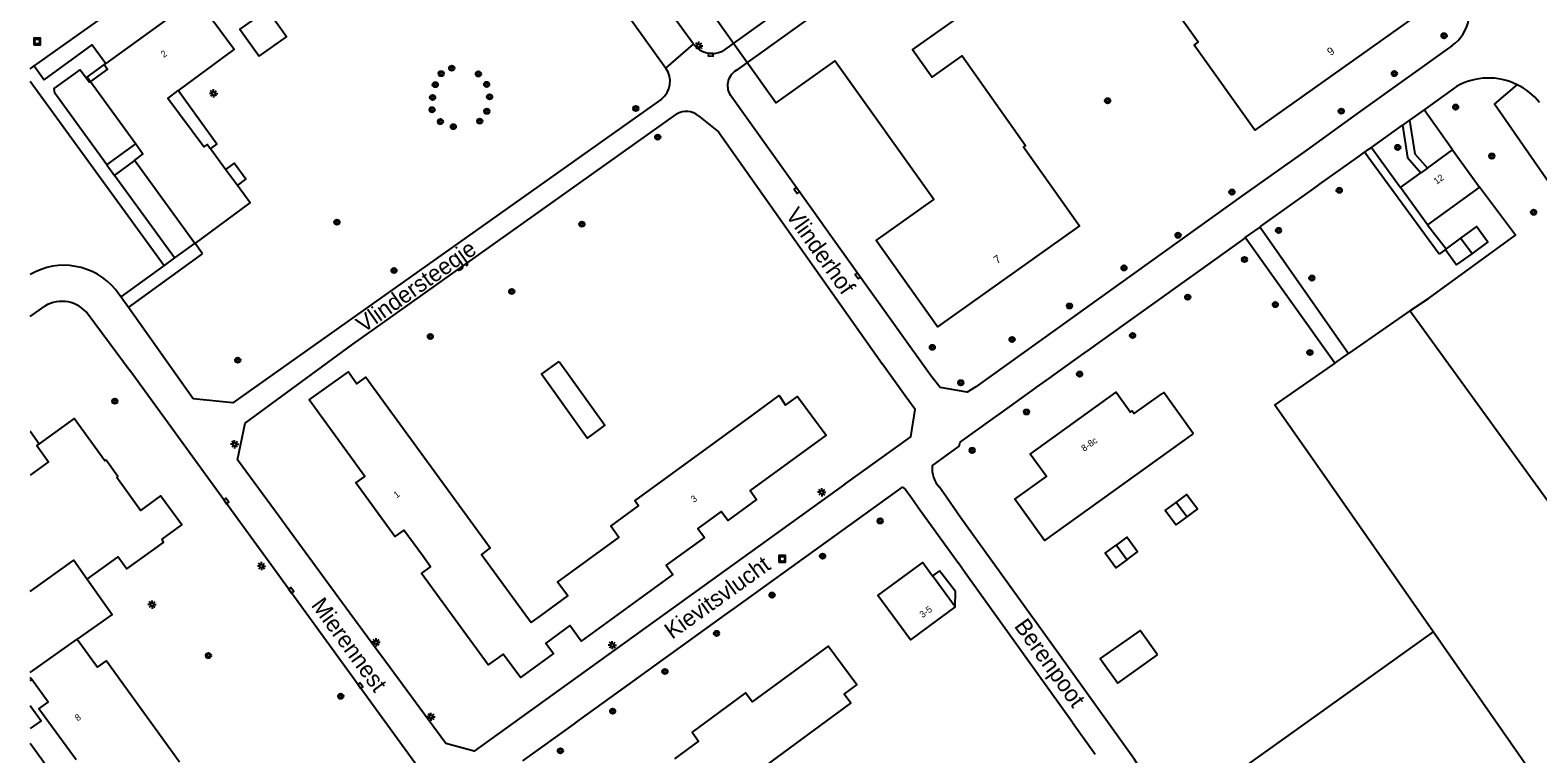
# Model space of a CAD drawing. Extents: x 141000 to 143000, y 400580 to 403500.
# Drawn here: x 141000 to 141228, y 402914.6 to 403024.1 of the extents above; entities that cross this region are included whole.
import ezdxf

# ---------------------------------------------------------------- set-up
doc = ezdxf.new("R2010")
doc.units = 0
for name, color, linetype in [('gg-afsc-erfafscheiding', 7, 'Continuous'), ('gg-afsc-muur', 7, 'Continuous'), ('gg-anno-huisnummerreeks BGT', 7, 'Continuous'), ('gg-anno-openbare ruimte label', 7, 'Continuous'), ('gg-bbg-bijgebouw', 7, 'Continuous'), ('gg-bbg-hoofdgebouw', 7, 'Continuous'), ('gg-bbg-luifel en loopbrug', 7, 'Continuous'), ('gg-bbg-overig bouwwerk', 7, 'Continuous'), ('gg-bbg-tussenscheiding', 7, 'Continuous'), ('gg-knt-verharding', 7, 'Continuous'), ('gg-knt-verharding nz', 7, 'Continuous'), ('gt-anno-plantopografie huisnummer', 7, 'Continuous'), ('gt-bbg-plantopografie pand', 7, 'Continuous'), ('gt-grn-groengrens', 7, 'Continuous'), ('gt-grn-vlakafsluiter', 7, 'Continuous'), ('gt-grn-weggrens', 7, 'Continuous'), ('gt-symb-boom', 7, 'Continuous'), ('gt-symb-kolk', 7, 'Continuous'), ('gt-symb-lichtmast', 7, 'Continuous'), ('gt-symb-rioolschacht', 7, 'Continuous')]:
    doc.layers.add(name, color=color, linetype=linetype)

# ---------------------------------------------------------------- blocks, each defined once
blk = doc.blocks.new('gt0-RS')
at = {"layer": 'gt-symb-rioolschacht'}
blk.add_lwpolyline([(-0.5, -0.5), (0.5, -0.5), (0.5, 0.5), (-0.5, 0.5)], close=True, dxfattribs=at)
blk.add_circle((0, 0), 0.375, dxfattribs=at)
blk = doc.blocks.new('gt0-KOLK')
at = {"layer": 'gt-symb-kolk'}
blk.add_lwpolyline([(0, 0), (0.37, 0), (0.37, 0.4), (-0.38, 0.4), (-0.38, 0), (0, 0)], dxfattribs=at)
blk = doc.blocks.new('gt0-LMAST')
at = {"layer": 'gt-symb-lichtmast'}
for p, q in [((-0.18, 0.17), (-0.45, 0.44)), ((-0.01, 0.25), (-0.01, 0.62)), ((0.17, 0.17), (0.44, 0.44)), ((-0.26, 0), (-0.63, 0)), ((-0.18, -0.18), (-0.45, -0.45)), ((-0.01, -0.25), (-0.01, -0.63)), ((0.44, -0.45), (0.17, -0.18)), ((0.24, 0), (0.62, 0))]:
    blk.add_line(p, q, dxfattribs=at)
blk.add_circle((-0.01, 0), 0.25, dxfattribs=at)
blk = doc.blocks.new('gt0-BOOM')
at = {"layer": 'gt-symb-boom'}
for radius in [0.4, 0.2]:
    blk.add_circle((0, 0), radius, dxfattribs=at)

msp = doc.modelspace()

# ---------------------------------------------------------------- linework, layer by layer
at = {"layer": 'gg-afsc-erfafscheiding'}
msp.add_lwpolyline([(141197.28, 402973.71), (141188.23, 402967.39), (141194.62, 402958.3)], dxfattribs=at)
at = {"layer": 'gg-afsc-muur'}
for points in [[(141002.1, 403016.55), (141009.38, 403021.86), (141011.43, 403019.05)], [(141000, 402963.36), (141000.03, 402963.39), (141001.35, 402961.53)]]:
    msp.add_lwpolyline(points, dxfattribs=at)
at = {"layer": 'gg-bbg-bijgebouw'}
for p, q in [((141216.29, 402992.6), (141214.09, 402990.99)), ((141218.03, 402990.27), (141216.29, 402992.6))]:
    msp.add_line(p, q, dxfattribs=at)
for points in [[(141034.65, 403020.12), (141038.76, 403023.06), (141035.82, 403027.17), (141031.71, 403024.23), (141034.65, 403020.12)], [(141214.09, 402990.99), (141213.98, 402990.91), (141214, 402990.88)], [(141214, 402990.88), (141215.7, 402988.56), (141218.03, 402990.27)], [(141079.99, 402973.98), (141086.91, 402964.32), (141084.22, 402962.39), (141077.3, 402972.05), (141079.99, 402973.98)], [(141174.88, 402950.45), (141173.23, 402949.24), (141171.62, 402951.42), (141173.27, 402952.63)], [(141173.27, 402952.63), (141174.92, 402953.84), (141176.52, 402951.66), (141174.88, 402950.45)], [(141165.81, 402943.99), (141167.46, 402945.2), (141165.85, 402947.39), (141164.2, 402946.18)], [(141165.81, 402943.99), (141164.16, 402942.78), (141162.55, 402944.97), (141164.2, 402946.18)]]:
    msp.add_lwpolyline(points, dxfattribs=at)
at = {"layer": 'gg-bbg-hoofdgebouw'}
for p, q in [((141011.43, 403019.05), (141011.18, 403018.87)), ((141009.11, 403016.3), (141015.96, 403006.87)), ((141015.81, 403004.34), (141024.89, 402991.85)), ((141029.56, 403002.99), (141027.25, 403006.11)), ((141211.28, 403003.22), (141215.06, 403005.96)), ((141215.06, 403005.96), (141219.13, 403000.34)), ((141031.35, 403000.58), (141029.56, 403002.99)), ((141207.2, 403000.27), (141210.3, 403002.51)), ((141211.28, 403003.22), (141210.3, 403002.51)), ((141211.27, 402994.65), (141207.2, 403000.27)), ((141219.13, 403000.34), (141211.27, 402994.65)), ((141024.89, 402991.85), (141024.93, 402991.8)), ((141139.89, 402936.88), (141136.44, 402941.54)), ((141000, 402926.93), (141007.12, 402931.96)), ((141000, 402926.24), (141000.26, 402925.89))]:
    msp.add_line(p, q, dxfattribs=at)
for points in [[(141025.45, 403028.48), (141025.08, 403028.99), (141011.43, 403019.05)], [(141022.4, 403014.93), (141022.57, 403015.05), (141030.83, 403021.16), (141027.52, 403025.66)], [(141011.18, 403018.87), (141011.68, 403018.18), (141009.11, 403016.3)], [(141027.25, 403006.11), (141027.14, 403006.26), (141026.76, 403006.77), (141026.28, 403006.41), (141020.83, 403013.76), (141022.4, 403014.93)], [(141015.96, 403006.87), (141017.06, 403005.35), (141015.76, 403004.41), (141015.81, 403004.34)], [(141024.93, 402991.8), (141033.28, 402997.97), (141031.35, 403000.58)], [(141075.75, 402934.47), (141077.1, 402935.46), (141081.28, 402938.51), (141079.75, 402940.61), (141089.03, 402947.37), (141087.8, 402949.06), (141092, 402952.12), (141091.45, 402952.88), (141109.24, 402965.85), (141113.26, 402968.82), (141114.24, 402967.35), (141116.05, 402968.69), (141120.38, 402962.83), (141108.85, 402954.45), (141109.85, 402953.08), (141105.48, 402949.9), (141104.48, 402951.27), (141100.98, 402948.71), (141101.97, 402947.35), (141097.99, 402944.45), (141096.19, 402943.14), (141097.17, 402941.76), (141083.33, 402931.67), (141081.61, 402934.02), (141077.99, 402931.36), (141079.12, 402929.82), (141074.12, 402926.15), (141071.53, 402929.72), (141069.27, 402928.07), (141059.17, 402941.92), (141060.54, 402942.92), (141059.31, 402944.62), (141056.51, 402948.48), (141055.13, 402947.48), (141049.23, 402955.59), (141050.6, 402956.59), (141042.21, 402968.15), (141048.12, 402972.41), (141049.42, 402970.59), (141050.78, 402971.58), (141069.58, 402945.78), (141068.23, 402944.79), (141075.75, 402934.47)], [(141175.75, 402962.99), (141153.37, 402946.9), (141148.91, 402953.13), (141153.66, 402956.55), (141151.23, 402959.97), (141164.22, 402969.31), (141166.4, 402966.3), (141166.65, 402966.48), (141166.95, 402966.09), (141171.11, 402969.07)], [(141175.75, 402962.99), (141175.85, 402963.07), (141171.41, 402969.29), (141171.11, 402969.07)], [(141008.63, 402941.04), (141013.32, 402944.43), (141014.62, 402942.6), (141020.16, 402946.58), (141019.94, 402947.09), (141022.93, 402949.28), (141019.73, 402953.65), (141016.68, 402951.42), (141013.1, 402956.44), (141013.28, 402956.57), (141011.49, 402959.05), (141011.31, 402958.92), (141006.65, 402965.32), (141001.35, 402961.53)], [(141001.35, 402961.53), (141001, 402961.28), (141002.78, 402958.79), (141000, 402956.79)], [(141000, 402939.19), (141006.58, 402943.92), (141008.63, 402941.04)], [(141139.89, 402936.88), (141135.86, 402933.91), (141133.12, 402931.88), (141131.16, 402934.54), (141128.19, 402938.56), (141134.96, 402943.55), (141136.44, 402941.54)], [(141007.12, 402931.96), (141010.16, 402927.73), (141011.53, 402928.71), (141022.6, 402913.4)], [(141098.3, 402903.28), (141124.07, 402922.27), (141123.07, 402923.63), (141125.01, 402925.05), (141120.67, 402930.93), (141109.19, 402922.5), (141108.19, 402923.85), (141100.08, 402917.93), (141101.08, 402916.56), (141097.43, 402913.85)], [(141006.94, 402913.7), (141001.33, 402921.45), (141002.73, 402922.44), (141000.26, 402925.89)]]:
    msp.add_lwpolyline(points, dxfattribs=at)
at = {"layer": 'gg-bbg-luifel en loopbrug'}
for p, q in [((141137.49, 402942.31), (141136.44, 402941.54)), ((141139.94, 402939.16), (141137.49, 402942.31)), ((141139.89, 402936.88), (141139.94, 402939.16))]:
    msp.add_line(p, q, dxfattribs=at)
for points in [[(141011.18, 403018.87), (141008.6, 403017), (141009.11, 403016.3)], [(141027.25, 403006.11), (141028.25, 403006.85), (141022.4, 403014.93)], [(141031.35, 403000.58), (141032.63, 403001.53), (141030.85, 403003.94), (141029.56, 403002.99)], [(141218.03, 402990.27), (141220.43, 402992.03), (141218.7, 402994.36), (141216.29, 402992.6)]]:
    msp.add_lwpolyline(points, dxfattribs=at)
at = {"layer": 'gg-bbg-overig bouwwerk'}
msp.add_lwpolyline([(141170.45, 402929.58), (141167.82, 402933.29), (141161.82, 402929.05), (141164.45, 402925.33), (141170.45, 402929.58)], dxfattribs=at)
at = {"layer": 'gg-bbg-tussenscheiding'}
for p, q in [((141174.88, 402950.45), (141173.27, 402952.63)), ((141165.81, 402943.99), (141164.2, 402946.18))]:
    msp.add_line(p, q, dxfattribs=at)
at = {"layer": 'gg-knt-verharding'}
for p, q in [((141068.88, 403056.29), (141096.13, 403018.32)), ((141143.59, 403048.84), (141104.67, 403020.9)), ((141107, 403018.12), (141146.54, 403046.54)), ((141100.29, 403021.95), (141093.27, 403031.68)), ((141000, 403018.23), (141000.61, 403018.66)), ((141000.61, 403018.66), (141002.1, 403016.55)), ((141000, 403016.35), (141020.25, 402988.47)), ((141215.68, 403015.55), (141210.78, 403012.04)), ((141053.26, 402979.78), (141097.74, 403011.36)), ((141210.78, 403012.04), (141208.59, 403010.48)), ((141202.8, 403006.34), (141207.5, 403009.7)), ((141208.59, 403010.48), (141207.5, 403009.7)), ((141011.58, 403003.7), (141015.96, 403006.87)), ((141012.73, 403002.1), (141015.81, 403004.34)), ((141200.97, 403005.03), (141201.77, 403005.6)), ((141213.05, 402990.18), (141201.77, 403005.6)), ((141202.8, 403006.34), (141207.2, 403000.27)), ((141021.81, 402989.62), (141012.73, 403002.1)), ((141193.53, 402999.71), (141194.88, 403000.68)), ((141183.74, 402992.71), (141185.97, 402994.3)), ((141197.28, 402973.71), (141183.74, 402992.71)), ((141185.97, 402994.3), (141199.37, 402975.17)), ((141211.27, 402994.65), (141214.09, 402990.99)), ((141024.89, 402991.85), (141021.81, 402989.62)), ((141214, 402990.88), (141213.05, 402990.18)), ((141020.25, 402988.47), (141013.73, 402983.73)), ((141014.88, 402982.14), (141026.06, 402990.25)), ((141013.73, 402983.73), (141012.91, 402984.83)), ((141000, 402980.76), (141002.22, 402982.35)), ((141024.65, 402968.34), (141014.88, 402982.14)), ((141008.75, 402981.1), (141015.1, 402972.54)), ((141127.93, 402974.93), (141128.89, 402973.58)), ((141154.52, 402971.74), (141159.74, 402975.49)), ((141161.04, 402976.42), (141159.74, 402975.49)), ((141197.28, 402973.71), (141199.37, 402975.17)), ((141146.83, 402966.22), (141152.09, 402970)), ((141145.61, 402965.35), (141146.83, 402966.22)), ((141138.09, 402954.09), (141137.5, 402954.94)), ((141133.3, 402953.3), (141134.6, 402951.47)), ((141134.6, 402951.47), (141140.35, 402943.45)), ((141141.39, 402942), (141140.35, 402943.45)), ((141157.6, 402919.39), (141141.39, 402942)), ((141105.11, 402935.66), (141107.02, 402937.03)), ((141093.5, 402927.28), (141105.11, 402935.66)), ((141091.12, 402925.57), (141093.5, 402927.28)), ((141000, 402925.7), (141000.26, 402925.89)), ((141084.3, 402920.65), (141091.12, 402925.57)), ((141082.48, 402919.34), (141084.3, 402920.65)), ((141082.48, 402919.34), (141074.46, 402913.56)), ((141157.6, 402919.39), (141161.06, 402914.56))]:
    msp.add_line(p, q, dxfattribs=at)
for points in [[(141000.61, 403018.66), (141001.04, 403018.97), (141024.96, 403035.95), (141026.63, 403037.14), (141054.27, 403056.76)], [(141214.95, 403021.72), (141201.53, 403012.07), (141200.26, 403011.16), (141192.95, 403005.9), (141183.48, 402999.15), (141143.01, 402970.14), (141141.67, 402969.32), (141137.6, 402970.02), (141136.24, 402971.73), (141120.17, 402994.22), (141118.93, 402995.97), (141105.84, 403014.28)], [(141011.58, 403003.7), (141003.73, 403014.56), (141003.65, 403015.23), (141007.58, 403018.08), (141008.96, 403016.19), (141009.11, 403016.3)], [(141253.98, 402970.33), (141252.64, 402969.38), (141232.6, 402996.73), (141221.43, 403012.86), (141224.86, 403015.82)], [(141095.46, 403013.63), (141030.65, 402967.72), (141024.65, 402968.34)], [(141101.05, 403011.13), (141104.08, 403008.69), (141127.93, 402974.93)], [(141207.5, 403009.7), (141208.27, 403004.82), (141210.3, 403002.51)], [(141208.59, 403010.48), (141209.4, 403005.35), (141211.28, 403003.22)], [(141194.88, 403000.68), (141194.93, 403000.71), (141200.61, 403004.77), (141200.97, 403005.03)], [(141201.77, 403005.6), (141202.03, 403005.79), (141202.34, 403006.01), (141202.8, 403006.34)], [(141185.97, 402994.3), (141186.06, 402994.37), (141193.41, 402999.62), (141193.53, 402999.71)], [(141183.74, 402992.71), (141183.51, 402992.54), (141161.04, 402976.42)], [(141123.19, 402955.42), (141067.14, 402915.05), (141062.83, 402916.21), (141053.71, 402928.58), (141052.25, 402930.57), (141047.1, 402937.61), (141045.15, 402940.26), (141039.11, 402948.52), (141037.64, 402950.52), (141031.37, 402959.08), (141032.5, 402964.65), (141048.79, 402976.6), (141053.26, 402979.78)], [(141027.72, 402886.58), (141036.67, 402893.06), (141038.3, 402894.24), (141057.86, 402908.39), (141058.57, 402912.71), (141036.38, 402943.26), (141032.61, 402948.44), (141015.1, 402972.54)], [(141123.19, 402955.42), (141133.15, 402962.59), (141133.81, 402966.69), (141132.29, 402968.76), (141128.89, 402973.58)], [(141152.09, 402970), (141152.1, 402970.01), (141154.47, 402971.71), (141154.52, 402971.74)], [(141136.38, 402958.2), (141140.46, 402961.14), (141140.63, 402961.77), (141145.61, 402965.35)], [(141107.02, 402937.03), (141131.9, 402954.96), (141132.35, 402954.62), (141133.3, 402953.3)], [(141155.48, 402929.78), (141152.25, 402934.27), (141151.29, 402935.61), (141140.68, 402950.38), (141138.09, 402954.09)], [(141008.63, 402941.04), (141012.42, 402935.7), (141007.12, 402931.96)], [(141172.66, 402904.85), (141168.19, 402911.18), (141167.76, 402912.56), (141166.97, 402913.79), (141155.48, 402929.78)], [(141000, 402921.94), (141001.68, 402919.62), (141000, 402918.48)], [(141000, 402916.23), (141010.64, 402901.5), (141012.07, 402902.47), (141023.04, 402887.22), (141027.72, 402886.58)]]:
    msp.add_lwpolyline(points, dxfattribs=at)
for centre, radius, start, end in [((141211.72, 403026.61), 5.86, 303.4572, 41.8905), ((141103.13, 403024.13), 3.58, 217.508, 295.5431), ((141093.32, 403016.33), 3.44, 308.3955, 35.3579), ((141108.16, 403015.67), 2.71, 115.3201, 210.9913), ((141220.53, 403007.02), 9.82, 63.7912, 119.5544), ((141220.54, 403007.04), 9.79, 38.3306, 63.8151), ((141099.24, 403008.96), 2.83, 50.0502, 121.8967), ((141005.12, 402978.42), 10.09, 39.452, 120.4936), ((141004.79, 402978.09), 4.97, 37.1405, 121.1482), ((141140.69, 402957.86), 4.32, 175.5046, 222.387)]:
    msp.add_arc(centre, radius, start, end, dxfattribs=at)
at = {"layer": 'gg-knt-verharding nz'}
for p, q in [((141011.58, 403003.7), (141012.73, 403002.1)), ((141021.81, 402989.62), (141020.25, 402988.47)), ((141014.88, 402982.14), (141013.73, 402983.73))]:
    msp.add_line(p, q, dxfattribs=at)
at = {"layer": 'gt-bbg-plantopografie pand'}
for points in [[(141211.54, 403027.68), (141185.2, 403008.94), (141176.03, 403021.83), (141176.6, 403022.24), (141165.33, 403038.08)], [(141151.63, 403034.08), (141133.43, 403021.13), (141136.4, 403016.96), (141140.91, 403020.17), (141150.53, 403006.64), (141150.21, 403006.41), (141158.69, 402994.48), (141137.2, 402979.2), (141127.92, 402992.25), (141136.63, 402998.45), (141121.69, 403019.45), (141112.74, 403013.09), (141103.5, 403026.08)]]:
    msp.add_lwpolyline(points, dxfattribs=at)
at = {"layer": 'gt-grn-groengrens'}
for p, q in [((141208.64, 402981.64), (141199.37, 402975.17)), ((141194.62, 402958.3), (141212.2, 402933.08))]:
    msp.add_line(p, q, dxfattribs=at)
msp.add_lwpolyline([(141212.2, 402933.08), (141232.48, 402904), (141253.94, 402919.11), (141208.64, 402981.64)], dxfattribs=at)
at = {"layer": 'gt-grn-vlakafsluiter'}
for p, q in [((141215.06, 403005.96), (141210.78, 403012.04)), ((141026.06, 402990.25), (141024.93, 402991.8)), ((141172.66, 402904.85), (141212.2, 402933.08))]:
    msp.add_line(p, q, dxfattribs=at)
msp.add_lwpolyline([(141208.64, 402981.64), (141211.43, 402983.49), (141224.61, 402993.09), (141219.13, 403000.34)], dxfattribs=at)
at = {"layer": 'gt-grn-weggrens'}
msp.add_line((141096.13, 403018.32), (141100.29, 403021.95), dxfattribs=at)

# ---------------------------------------------------------------- block references
at = {"layer": 'gt-symb-boom'}
for p in [(141213.8, 403023.24), (141062.15, 403017.5), (141063.75, 403018.33), (141067.78, 403017.46), (141206.29, 403017.51), (141061.26, 403015.83), (141069.03, 403015.87), (141060.86, 403013.9), (141069.47, 403013.99), (141162.92, 403013.4), (141060.78, 403012.04), (141069.05, 403011.81), (141091.58, 403012.23), (141198.25, 403011.82), (141215.55, 403012.44), (141062.04, 403010.25), (141063.99, 403009.48), (141067.99, 403010.31), (141094.89, 403007.9), (141206.8, 403006.35), (141221.02, 403005.04), (141181.72, 402999.59), (141197.95, 402999.85), (141046.39, 402995.04), (141083.43, 402994.74), (141227.33, 402996.53), (141173.58, 402993.06), (141188.77, 402993.79), (141055.02, 402987.72), (141165.4, 402988.11), (141183.62, 402989.39), (141193.81, 402986.58), (141072.82, 402984.55), (141175.03, 402983.7), (141157.16, 402982.36), (141188.28, 402982.57), (141060.51, 402977.75), (141148.47, 402977.3), (141166.7, 402977.89), (141031.39, 402974.16), (141136.42, 402976.11), (141193.52, 402975.33), (141158.69, 402972.07), (141140.73, 402970.75), (141012.8, 402967.96), (141150.66, 402966.33), (141142.44, 402960.52), (141128.53, 402949.85), (141119.83, 402944.53), (141112.18, 402938.64), (141103.79, 402932.84), (141026.96, 402929.48), (141095.98, 402927.08), (141046.96, 402923.34), (141088.08, 402921.08), (141080.18, 402915.09)]:
    msp.add_blockref('gt0-BOOM', p, dxfattribs=at)
at = {"layer": 'gt-symb-kolk'}
for p, rotation in [((141102.92, 403020.56), 177.09366989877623), ((141116.09, 402999.94), 125.5479964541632), ((141125.31, 402987.04), 125.5479964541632), ((141029.49, 402952.74), -53.99517092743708), ((141039.31, 402939.22), -54.00169931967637), ((141049.75, 402924.84), -54.00169931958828)]:
    msp.add_blockref('gt0-KOLK', p, dxfattribs=dict(at, rotation=rotation))
at = {"layer": 'gt-symb-lichtmast'}
for p in [(141101.12, 403021.72), (141027.74, 403014.52), (141030.93, 402961.46), (141119.7, 402954.18), (141034.99, 402943.03), (141018.44, 402937.21), (141052.32, 402931.5), (141088.03, 402931.07), (141060.61, 402920.23)]:
    msp.add_blockref('gt0-LMAST', p, dxfattribs=at)
at = {"layer": 'gt-symb-rioolschacht'}
for p in [(141001.06, 403022.36), (141113.73, 402944.11)]:
    msp.add_blockref('gt0-RS', p, dxfattribs=at)

# ---------------------------------------------------------------- texts
at = {"layer": 'gg-anno-huisnummerreeks BGT'}
for s, rotation, p in [('2', 36, (141020.2, 403019.87)), ('12', 35.9, (141212.67, 403000.69)), ('8-8c', 35.7, (141159.38, 402960.29)), ('1', 36, (141055.4, 402953.25)), ('3', 36.2, (141100.35, 402952.58)), ('3-5', 36.4, (141134.94, 402935.14)), ('8', 35.9, (141007.19, 402919.51))]:
    msp.add_text(s, height=1, rotation=rotation, dxfattribs=at).set_placement(p)
at = {"layer": 'gg-anno-openbare ruimte label'}
for s, rotation, p in [('Vlinderhof', 305.4, (141114.14, 402996.11)), ('Vlindersteegje', 35.3, (141050.42, 402978.21)), ('Kievitsvlucht', 35.6, (141097.06, 402931.87)), ('Mierennest', 306.1, (141042.39, 402937.09)), ('Berenpoot', 305.7, (141148.7, 402933.94))]:
    msp.add_text(s, height=2.5, rotation=rotation, dxfattribs=at).set_placement(p)
at = {"layer": 'gt-anno-plantopografie huisnummer'}
for s, p in [('9', (141196.64, 403020.14)), ('7', (141146.21, 402988.68))]:
    msp.add_text(s, height=1.2, rotation=35.4317, dxfattribs=at).set_placement(p)

doc.saveas('drawing.dxf')
